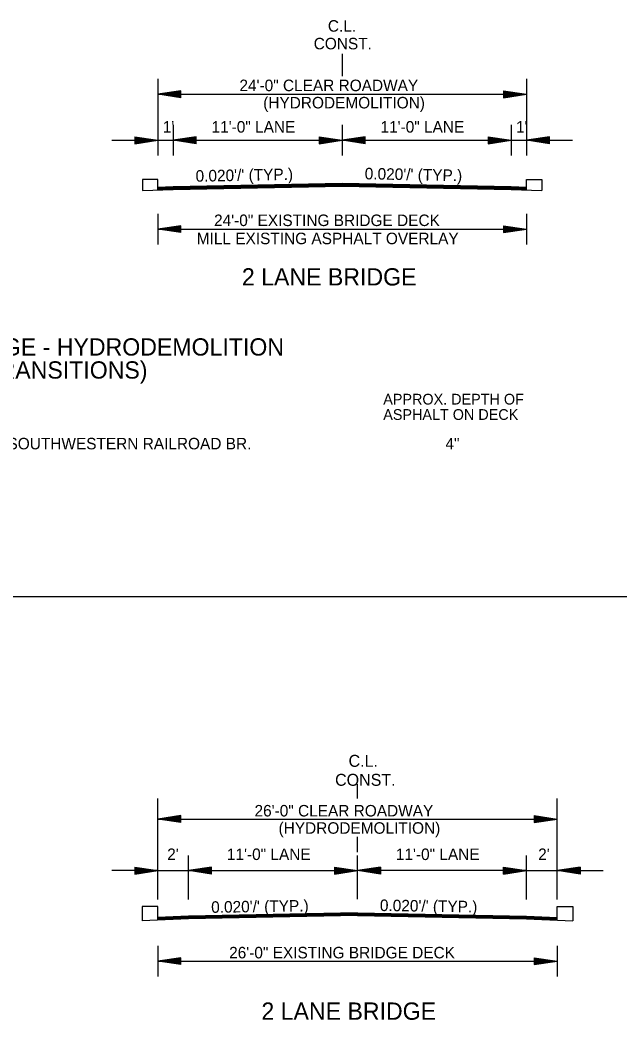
# Model space of a CAD drawing. Extents: x 549600 to 1930787, y -1955432 to 596640.
# Drawn here: x 551632 to 552023, y -1954032 to -1953381 of the extents above; entities that cross this region are included whole.
import ezdxf

# ---------------------------------------------------------------- set-up
doc = ezdxf.new("R2010")
doc.units = 0
for name, color, linetype in [('R_Border', 7, 'Continuous'), ('R_Border Notes', 7, 'Continuous'), ('S_AREA_CALC', 7, 'Continuous')]:
    doc.layers.add(name, color=color, linetype=linetype)

# ---------------------------------------------------------------- blocks, each defined once
blk = doc.blocks.new('ARROW')
at = {"layer": 'S_AREA_CALC'}
for p, q in [((-2, 0.3), (0, 0)), ((-2, 0.3), (-2, -0.3)), ((-2, 0.25), (-0.334, 0)), ((-2, 0.199), (-0.678, 0)), ((-2, 0.149), (-1.011, 0)), ((-2, 0.097), (-1.35, 0)), ((-2, 0.047), (-1.684, 0)), ((-2, -0.3), (0, 0)), ((-2, -0.098), (-1.35, 0)), ((-2, -0.199), (-0.678, 0)), ((-2, -0.25), (-0.334, 0)), ((-2, -0.149), (-1.011, 0)), ((-2, -0.047), (-1.684, 0))]:
    blk.add_line(p, q, dxfattribs=at)

msp = doc.modelspace()

# ---------------------------------------------------------------- linework, layer by layer
at = {"layer": 'R_Border'}
for p, q in [((551842.02, -1953402.71), (551842.02, -1953417.21)), ((551722.02, -1953418.93), (551722.02, -1953468.93)), ((551962.02, -1953418.93), (551962.02, -1953468.93)), ((551722.02, -1953428.93), (551962.02, -1953428.93)), ((551732.02, -1953448.93), (551732.02, -1953468.93)), ((551842.02, -1953448.93), (551842.02, -1953468.93)), ((551952.02, -1953448.93), (551952.02, -1953468.93)), ((551692.02, -1953458.93), (551992.02, -1953458.93)), ((551722.02, -1953506.79), (551722.02, -1953526.79)), ((551962.02, -1953506.79), (551962.02, -1953526.79)), ((551722.02, -1953516.79), (551962.02, -1953516.79)), ((551008.97, -1953755.99), (552070.24, -1953755.99)), ((551982.02, -1953934.49), (552012.02, -1953934.49)), ((551711.85, -1953957.8), (551711.84, -1953967.18)), ((551722.02, -1953957.8), (551711.85, -1953957.8)), ((551722.02, -1953966.6), (551722.02, -1953957.8)), ((551982.02, -1953966.6), (551982.02, -1953957.8)), ((551982.02, -1953957.8), (551992.18, -1953957.8)), ((551992.18, -1953957.8), (551992.2, -1953967.18))]:
    msp.add_line(p, q, dxfattribs=at)
for points in [[(551722.02, -1953491.03), (551722.02, -1953484.53), (551712.02, -1953484.53), (551712.02, -1953491.73)], [(551712.02, -1953491.73), (551732.02, -1953490.93), (551842.02, -1953488.73), (551952.02, -1953490.93), (551972.02, -1953491.73)], [(551722.02, -1953489.53), (551732.02, -1953489.13), (551842.02, -1953486.93), (551952.02, -1953489.13), (551962.02, -1953489.53)], [(551722.02, -1953489.83), (551732.02, -1953489.43), (551842.02, -1953487.23), (551952.02, -1953489.43), (551962.02, -1953489.83)], [(551722.02, -1953490.13), (551732.02, -1953489.73), (551842.02, -1953487.53), (551952.02, -1953489.73), (551962.02, -1953490.13)], [(551722.02, -1953490.43), (551732.02, -1953490.03), (551842.02, -1953487.83), (551952.02, -1953490.03), (551962.02, -1953490.43)], [(551722.02, -1953490.73), (551732.02, -1953490.33), (551842.02, -1953488.13), (551952.02, -1953490.33), (551962.02, -1953490.73)], [(551722.02, -1953491.03), (551732.02, -1953490.63), (551842.02, -1953488.43), (551952.02, -1953490.63), (551962.02, -1953491.03)], [(551962.02, -1953491.73), (551962.02, -1953484.53), (551972.02, -1953484.53), (551972.02, -1953491.73)]]:
    msp.add_lwpolyline(points, dxfattribs=at)
at = {"layer": 'S_AREA_CALC'}
for p, q in [((551852.02, -1953887.54), (551852.02, -1953878.24)), ((551722.02, -1953953.32), (551722.02, -1953887.59)), ((551982.02, -1953953.32), (551982.02, -1953887.59)), ((551737.02, -1953898.7), (551722.02, -1953900.95)), ((551737.02, -1953899.08), (551724.52, -1953900.95)), ((551737.02, -1953899.46), (551727.1, -1953900.95)), ((551737.02, -1953899.84), (551729.6, -1953900.95)), ((551737.02, -1953903.2), (551737.02, -1953898.7)), ((551967.02, -1953898.7), (551982.02, -1953900.95)), ((551967.02, -1953898.7), (551967.02, -1953903.2)), ((551967.02, -1953899.08), (551979.51, -1953900.95)), ((551967.02, -1953899.46), (551976.93, -1953900.95)), ((551967.02, -1953899.84), (551974.44, -1953900.95)), ((551722.02, -1953900.95), (551980.02, -1953900.95)), ((551737.02, -1953903.2), (551722.02, -1953900.95)), ((551737.02, -1953902.83), (551724.52, -1953900.95)), ((551737.02, -1953902.45), (551727.1, -1953900.95)), ((551737.02, -1953902.07), (551729.6, -1953900.95)), ((551737.02, -1953900.22), (551732.14, -1953900.95)), ((551737.02, -1953901.68), (551732.14, -1953900.95)), ((551737.02, -1953900.6), (551734.65, -1953900.95)), ((551737.02, -1953901.31), (551734.65, -1953900.95)), ((551967.02, -1953900.23), (551971.89, -1953900.95)), ((551967.02, -1953900.6), (551969.39, -1953900.95)), ((551967.02, -1953903.2), (551982.02, -1953900.95)), ((551967.02, -1953901.69), (551971.89, -1953900.95)), ((551967.02, -1953902.45), (551976.93, -1953900.95)), ((551967.02, -1953902.83), (551979.51, -1953900.95)), ((551967.02, -1953902.07), (551974.44, -1953900.95)), ((551967.02, -1953901.31), (551969.39, -1953900.95)), ((551852.02, -1953922.48), (551852.02, -1953912.61)), ((551742.02, -1953953.32), (551742.02, -1953924.6)), ((551852.02, -1953953.15), (551852.02, -1953924.6)), ((551962.02, -1953953.32), (551962.02, -1953924.6)), ((551707.02, -1953932.24), (551722.02, -1953934.49)), ((551707.02, -1953932.24), (551707.02, -1953936.74)), ((551707.02, -1953932.62), (551719.51, -1953934.49)), ((551757.02, -1953932.24), (551742.02, -1953934.49)), ((551757.02, -1953932.62), (551744.52, -1953934.49)), ((551757.02, -1953936.74), (551757.02, -1953932.24)), ((551837.02, -1953932.24), (551852.02, -1953934.49)), ((551837.02, -1953932.24), (551837.02, -1953936.74)), ((551837.02, -1953932.62), (551849.51, -1953934.49)), ((551867.02, -1953932.24), (551852.02, -1953934.49)), ((551867.02, -1953932.62), (551854.52, -1953934.49)), ((551867.02, -1953932.24), (551867.02, -1953936.74)), ((551947.02, -1953932.24), (551962.02, -1953934.49)), ((551947.02, -1953936.74), (551947.02, -1953932.24)), ((551947.02, -1953932.62), (551959.51, -1953934.49)), ((551997.02, -1953932.24), (551982.02, -1953934.49)), ((551997.02, -1953932.62), (551984.52, -1953934.49)), ((551997.02, -1953932.24), (551997.02, -1953936.74)), ((551722.02, -1953934.49), (551692.02, -1953934.49)), ((551707.02, -1953933), (551716.93, -1953934.49)), ((551707.02, -1953933.37), (551714.44, -1953934.49)), ((551707.02, -1953933.76), (551711.89, -1953934.49)), ((551707.02, -1953934.14), (551709.39, -1953934.49)), ((551707.02, -1953936.74), (551722.02, -1953934.49)), ((551707.02, -1953935.23), (551711.89, -1953934.49)), ((551707.02, -1953935.98), (551716.93, -1953934.49)), ((551707.02, -1953936.37), (551719.51, -1953934.49)), ((551707.02, -1953935.61), (551714.44, -1953934.49)), ((551707.02, -1953934.84), (551709.39, -1953934.49)), ((551722.02, -1953934.49), (551742.02, -1953934.49)), ((551757.02, -1953936.74), (551742.02, -1953934.49)), ((551742.02, -1953934.49), (551852.02, -1953934.49)), ((551757.02, -1953936.37), (551744.52, -1953934.49)), ((551757.02, -1953933), (551747.1, -1953934.49)), ((551757.02, -1953935.98), (551747.1, -1953934.49)), ((551757.02, -1953933.37), (551749.6, -1953934.49)), ((551757.02, -1953935.61), (551749.6, -1953934.49)), ((551757.02, -1953933.76), (551752.14, -1953934.49)), ((551757.02, -1953935.22), (551752.14, -1953934.49)), ((551757.02, -1953934.14), (551754.65, -1953934.49)), ((551757.02, -1953934.84), (551754.65, -1953934.49)), ((551837.02, -1953933), (551846.93, -1953934.49)), ((551837.02, -1953933.37), (551844.44, -1953934.49)), ((551837.02, -1953933.76), (551841.89, -1953934.49)), ((551837.02, -1953934.14), (551839.39, -1953934.49)), ((551837.02, -1953936.74), (551852.02, -1953934.49)), ((551837.02, -1953935.23), (551841.89, -1953934.49)), ((551837.02, -1953935.98), (551846.93, -1953934.49)), ((551837.02, -1953936.37), (551849.51, -1953934.49)), ((551837.02, -1953935.61), (551844.44, -1953934.49)), ((551837.02, -1953934.84), (551839.39, -1953934.49)), ((551962.02, -1953934.49), (551852.02, -1953934.49)), ((551867.02, -1953936.74), (551852.02, -1953934.49)), ((551867.02, -1953936.37), (551854.52, -1953934.49)), ((551867.02, -1953933), (551857.1, -1953934.49)), ((551867.02, -1953935.98), (551857.1, -1953934.49)), ((551867.02, -1953933.37), (551859.6, -1953934.49)), ((551867.02, -1953935.61), (551859.6, -1953934.49)), ((551867.02, -1953933.76), (551862.14, -1953934.49)), ((551867.02, -1953935.23), (551862.14, -1953934.49)), ((551867.02, -1953934.14), (551864.65, -1953934.49)), ((551867.02, -1953934.84), (551864.65, -1953934.49)), ((551947.02, -1953933), (551956.93, -1953934.49)), ((551947.02, -1953933.37), (551954.44, -1953934.49)), ((551947.02, -1953933.76), (551951.89, -1953934.49)), ((551947.02, -1953934.14), (551949.39, -1953934.49)), ((551947.02, -1953936.74), (551962.02, -1953934.49)), ((551947.02, -1953935.22), (551951.89, -1953934.49)), ((551947.02, -1953935.98), (551956.93, -1953934.49)), ((551947.02, -1953936.37), (551959.51, -1953934.49)), ((551947.02, -1953935.61), (551954.44, -1953934.49)), ((551947.02, -1953934.84), (551949.39, -1953934.49)), ((551962.02, -1953934.49), (551982.02, -1953934.49)), ((551997.02, -1953936.74), (551982.02, -1953934.49)), ((551997.02, -1953936.37), (551984.52, -1953934.49)), ((551997.02, -1953933), (551987.1, -1953934.49)), ((551997.02, -1953935.98), (551987.1, -1953934.49)), ((551997.02, -1953933.37), (551989.6, -1953934.49)), ((551997.02, -1953935.61), (551989.6, -1953934.49)), ((551997.02, -1953933.76), (551992.14, -1953934.49)), ((551997.02, -1953935.23), (551992.14, -1953934.49)), ((551997.02, -1953934.14), (551994.65, -1953934.49)), ((551997.02, -1953934.84), (551994.65, -1953934.49)), ((551742.02, -1953964.3), (551722.02, -1953965.1)), ((551742.02, -1953964.6), (551722.02, -1953965.4)), ((551742.02, -1953964.9), (551722.02, -1953965.7)), ((551742.02, -1953965.2), (551722.02, -1953966)), ((551852.02, -1953962.1), (551742.02, -1953964.3)), ((551852.02, -1953962.4), (551742.02, -1953964.6)), ((551852.03, -1953962.7), (551742.02, -1953964.9)), ((551852.04, -1953963), (551742.02, -1953965.2)), ((551852.04, -1953963.3), (551742.02, -1953965.5)), ((551852.05, -1953963.6), (551742.02, -1953965.8)), ((551852.05, -1953963.77), (551742.02, -1953965.97)), ((551851.98, -1953963.77), (551962.02, -1953965.97)), ((551851.99, -1953963.3), (551962.02, -1953965.5)), ((551851.99, -1953963.6), (551962.02, -1953965.8)), ((551852, -1953963), (551962.02, -1953965.2)), ((551852.01, -1953962.4), (551962.02, -1953964.6)), ((551852.01, -1953962.7), (551962.02, -1953964.9)), ((551852.02, -1953962.1), (551962.02, -1953964.3)), ((551962.02, -1953964.3), (551982.02, -1953965.1)), ((551962.02, -1953964.6), (551982.02, -1953965.4)), ((551962.02, -1953964.9), (551982.02, -1953965.7)), ((551962.02, -1953965.2), (551982.02, -1953966)), ((551742.02, -1953965.97), (551711.84, -1953967.18)), ((551742.02, -1953965.5), (551722.02, -1953966.3)), ((551742.02, -1953965.8), (551722.02, -1953966.6)), ((551962.02, -1953965.5), (551982.02, -1953966.3)), ((551962.02, -1953965.8), (551982.02, -1953966.6)), ((551962.02, -1953965.97), (551992.2, -1953967.18)), ((551722.02, -1953983.51), (551722.02, -1954003.51)), ((551982.02, -1953983.51), (551982.02, -1954003.51)), ((551737.02, -1953991.26), (551722.02, -1953993.51)), ((551737.02, -1953995.76), (551737.02, -1953991.26)), ((551967.02, -1953991.26), (551982.02, -1953993.51)), ((551967.02, -1953991.26), (551967.02, -1953995.76)), ((551722.02, -1953993.51), (551982.02, -1953993.51)), ((551737.02, -1953995.76), (551722.02, -1953993.51)), ((551737.02, -1953991.63), (551724.52, -1953993.51)), ((551737.02, -1953995.38), (551724.52, -1953993.51)), ((551737.02, -1953992.01), (551727.1, -1953993.51)), ((551737.02, -1953995), (551727.1, -1953993.51)), ((551737.02, -1953992.39), (551729.6, -1953993.51)), ((551737.02, -1953994.62), (551729.6, -1953993.51)), ((551737.02, -1953992.77), (551732.14, -1953993.51)), ((551737.02, -1953994.23), (551732.14, -1953993.51)), ((551737.02, -1953993.15), (551734.65, -1953993.51)), ((551737.02, -1953993.86), (551734.65, -1953993.51)), ((551967.02, -1953991.63), (551979.51, -1953993.51)), ((551967.02, -1953992.01), (551976.93, -1953993.51)), ((551967.02, -1953992.39), (551974.44, -1953993.51)), ((551967.02, -1953992.78), (551971.89, -1953993.51)), ((551967.02, -1953993.15), (551969.39, -1953993.51)), ((551967.02, -1953995.76), (551982.02, -1953993.51)), ((551967.02, -1953994.24), (551971.89, -1953993.51)), ((551967.02, -1953995), (551976.93, -1953993.51)), ((551967.02, -1953995.38), (551979.51, -1953993.51)), ((551967.02, -1953994.62), (551974.44, -1953993.51)), ((551967.02, -1953993.86), (551969.39, -1953993.51))]:
    msp.add_line(p, q, dxfattribs=at)

# ---------------------------------------------------------------- block references
at = {"layer": 'R_Border', "xscale": 7.5, "yscale": 7.5, "rotation": 180}
for p in [(551722.02, -1953428.93), (551732.02, -1953458.93), (551842.02, -1953458.93), (551962.02, -1953458.93), (551722.02, -1953516.79)]:
    msp.add_blockref('ARROW', p, dxfattribs=at)
at = {"layer": 'R_Border', "xscale": 7.5, "yscale": 7.5}
for p in [(551962.02, -1953428.93), (551722.02, -1953458.93), (551842.02, -1953458.93), (551952.02, -1953458.93), (551962.02, -1953516.79)]:
    msp.add_blockref('ARROW', p, dxfattribs=at)

# ---------------------------------------------------------------- texts
at = {"layer": 'R_Border'}
for s, height, p in [('C.L.', 7.5, (551832.69, -1953388.21)), ('CONST.', 7.5, (551823.47, -1953399.71)), ('24\'-0" CLEAR ROADWAY', 7.5, (551775.11, -1953426.93)), ('(HYDRODEMOLITION)', 7.5, (551790.58, -1953438.18)), ("1'", 7.5, (551725.19, -1953453.93)), ('11\'-0" LANE', 7.5, (551756.96, -1953453.93)), ('11\'-0" LANE', 7.5, (551866.96, -1953453.93)), ("1'", 7.5, (551955.19, -1953453.93)), ('24\'-0" EXISTING BRIDGE DECK', 7.5, (551758.57, -1953514.79)), ('2 LANE BRIDGE', 11.25, (551776.7, -1953553.49)), ('24 FT. CLEAR ROADWAY BRIDGE - HYDRODEMOLITION', 11.25, (551401.23, -1953599.12)), ('(ROADWAY TRANSITIONS)', 11.25, (551522.18, -1953614.12)), ('- BR NO. 01978 - HWY. 79: ST. LOUIS SOUTHWESTERN RAILROAD BR.', 7.5, (551446.84, -1953660.2)), ('4"', 7.5, (551909.27, -1953660.2))]:
    msp.add_text(s, height=height, dxfattribs=at).set_placement(p)
for rotation, p in [(358.8542, (551856.63, -1953484.32)), (1.1458, (551746.63, -1953485.94))]:
    msp.add_text("0.020'/' (TYP.)", height=7.5, rotation=rotation, dxfattribs=at).set_placement(p)
at = {"layer": 'R_Border Notes'}
for s, p in [('APPROX. DEPTH OF', (551868.75, -1953631.02)), ('ASPHALT ON DECK', (551868.75, -1953641.02))]:
    msp.add_text(s, height=7, dxfattribs=at).set_placement(p)
at = {"layer": 'S_AREA_CALC'}
for s, height, p in [('MILL EXISTING ASPHALT OVERLAY', 7.5, (551747.29, -1953526.59)), ('C.L.', 7.8, (551846.17, -1953866.94)), ('CONST.', 7.8, (551837.39, -1953879.31)), ('26\'-0" CLEAR ROADWAY ', 7.5, (551784.93, -1953899.28)), ('(HYDRODEMOLITION)', 7.5, (551800.58, -1953910.53)), ("2'", 7.5, (551728.06, -1953927.63)), ('11\'-0" LANE', 7.5, (551766.96, -1953927.63)), ('11\'-0" LANE', 7.5, (551876.96, -1953927.63)), ("2'", 7.5, (551969.62, -1953927.63)), ('26\'-0" EXISTING BRIDGE DECK', 7.5, (551768.4, -1953991.68)), ('2 LANE BRIDGE', 11.25, (551789.42, -1954031.65))]:
    msp.add_text(s, height=height, dxfattribs=at).set_placement(p)
for rotation, p in [(0.87191, (551756.76, -1953962.05)), (359.12809, (551866.51, -1953960.82))]:
    msp.add_text("0.020'/' (TYP.)", height=7.5, rotation=rotation, dxfattribs=at).set_placement(p)

doc.saveas('drawing.dxf')
